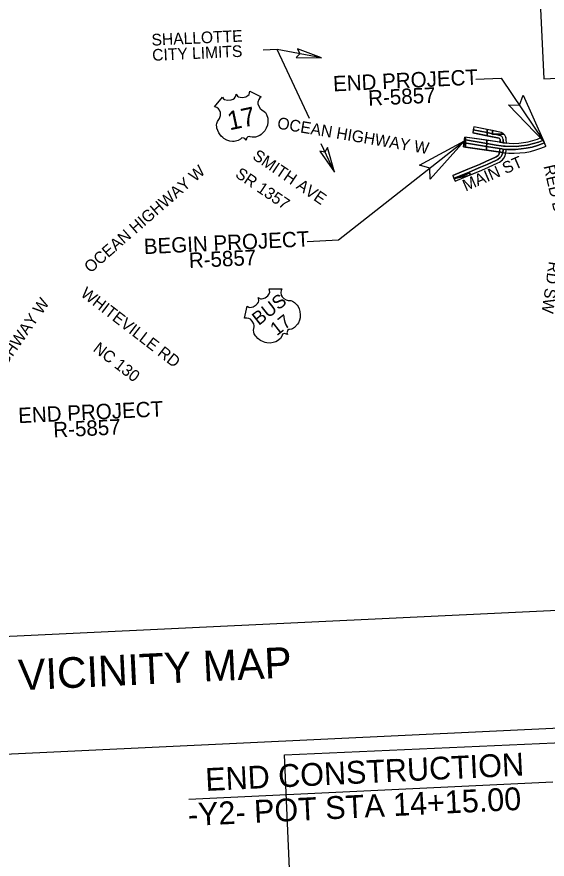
# Model space of a CAD drawing. Extents: x 2170913 to 2188101, y 74009 to 87693.
# Drawn here: x 2173761 to 2175486, y 78286 to 81028 of the extents above; entities that cross this region are included whole.
import ezdxf

# ---------------------------------------------------------------- set-up
doc = ezdxf.new("R2010")
doc.units = 0
for name, color, linetype in [('CTL Primary Horizontal and Vertical Cogo Elevation', 7, 'Continuous'), ('Exist Other Culture Fence Line', 7, 'Continuous'), ('Exist Property Iron Pin CELL', 7, 'Continuous'), ('Exist Right of Way Monument CELL', 7, 'Continuous'), ('Exist Structure Minor Pipes HDPE 30 Inch', 7, 'Continuous'), ('Exist Structure Minor Pipes RCP 15 Inch', 7, 'Continuous'), ('Exist Structure Minor Storm Sewer Manhole CELL', 7, 'Continuous'), ('Exist Utilities Water Fire Hydrant CELL', 7, 'Continuous')]:
    doc.layers.add(name, color=color, linetype=linetype)

msp = doc.modelspace()

# ---------------------------------------------------------------- linework, layer by layer
at = {"layer": 'CTL Primary Horizontal and Vertical Cogo Elevation'}
for p, q in [((2174607.1, 80921.5), (2174561.9, 80919.4)), ((2174752.1, 80894.4), (2174607.1, 80921.5)), ((2174712.2, 80696.8), (2174607.1, 80921.5)), ((2175253.5, 80824.7), (2175336.8, 80828.7)), ((2175336.8, 80828.7), (2175475.5, 80621.7)), ((2174807.2, 80302), (2175216.5, 80624.3)), ((2174793.6, 80522.8), (2174750.5, 80614.8)), ((2174705.2, 80297.1), (2174807.2, 80302)), ((2172841.7, 78585.3), (2175789.7, 78725.5))]:
    msp.add_line(p, q, dxfattribs=at)
for points in [[(2172704.4, 81472.7), (2175652.3, 81612.9), (2175771.5, 79107.1), (2172823.6, 78966.9)], [(2175652.3, 81612.9), (2175437.7, 81602.7), (2175474.6, 80826.6), (2175689.2, 80836.8)]]:
    msp.add_lwpolyline(points, close=True, dxfattribs=at)
at = {"layer": 'Exist Other Culture Fence Line'}
for points in [[(2174403.8, 80735.6), (2174429.7, 80767.1), (2174432.9, 80761.5), (2174435.7, 80759.3), (2174445.7, 80756.3), (2174457.6, 80757.6), (2174464.2, 80760.3), (2174468.2, 80763), (2174471.3, 80766.1), (2174474.5, 80774), (2174474.3, 80776.6), (2174478.8, 80769.8), (2174481.7, 80768.1), (2174486.8, 80766.3), (2174494.6, 80765.8), (2174505.1, 80768), (2174512, 80771.8), (2174516, 80775.7), (2174518.9, 80786.1), (2174555.4, 80767.9), (2174551.1, 80764.2), (2174547.5, 80759), (2174545.1, 80750.6), (2174545.1, 80744.6), (2174547.4, 80736.8), (2174552.1, 80729.8), (2174557.7, 80725.1), (2174565.1, 80720.4), (2174569.2, 80716.3), (2174573, 80710.3), (2174577.1, 80698.1), (2174577.6, 80692.6), (2174577.5, 80685), (2174575.8, 80675.7), (2174572, 80665.5), (2174567.4, 80657.4), (2174562.4, 80651.2), (2174555.3, 80644.6), (2174550.9, 80641.6), (2174537, 80636.4), (2174529.7, 80635.9), (2174525.8, 80636.3), (2174519.9, 80637.9), (2174517.7, 80638.7), (2174512.3, 80637.9), (2174508.7, 80634.3), (2174507.3, 80631.9), (2174506.2, 80626.3), (2174501.9, 80631.6), (2174498.7, 80633.5), (2174492.3, 80634.2), (2174487.7, 80630), (2174480.2, 80625.1), (2174467.8, 80621.9), (2174462.2, 80621.8), (2174453.3, 80623.1), (2174443.5, 80626.6), (2174434.2, 80632), (2174430.3, 80635.1), (2174425.5, 80639.6), (2174419.4, 80647.3), (2174417.3, 80650.7), (2174414, 80657.7), (2174411.7, 80665.4), (2174411.2, 80668.8), (2174410, 80676.4), (2174411.7, 80681.2), (2174413.8, 80687.5), (2174419.9, 80697), (2174421.4, 80700), (2174423.3, 80706.5), (2174423.1, 80716.4), (2174420.3, 80724), (2174416.4, 80729.1), (2174411.3, 80733), (2174404.3, 80735.5), (2174403.8, 80735.6), (2174429.7, 80767.1)], [(2174500.7, 80046.6), (2174510.1, 80086.2), (2174515.4, 80082.6), (2174518.9, 80081.9), (2174529.2, 80083.7), (2174539.4, 80090.1), (2174544, 80095.3), (2174546.4, 80099.6), (2174547.9, 80103.7), (2174547.3, 80112.2), (2174545.9, 80114.5), (2174553, 80110.4), (2174556.3, 80110), (2174561.7, 80110.8), (2174568.9, 80113.7), (2174577.3, 80120.3), (2174581.8, 80126.8), (2174583.7, 80132.1), (2174581.7, 80142.7), (2174622.5, 80142.5), (2174620.3, 80137.3), (2174619.3, 80131), (2174620.9, 80122.3), (2174623.6, 80117), (2174629.1, 80111), (2174636.3, 80106.8), (2174643.5, 80105.1), (2174652.2, 80104.1), (2174657.7, 80102.2), (2174663.7, 80098.6), (2174672.8, 80089.4), (2174675.8, 80084.7), (2174678.9, 80077.9), (2174681.5, 80068.8), (2174682.7, 80057.9), (2174682.1, 80048.6), (2174680.4, 80040.8), (2174676.9, 80031.8), (2174674.2, 80027.2), (2174664.1, 80016.3), (2174657.7, 80012.6), (2174654.1, 80011.3), (2174648, 80010.2), (2174645.7, 80009.9), (2174641.3, 80006.7), (2174639.6, 80001.9), (2174639.4, 79999.2), (2174640.9, 79993.6), (2174634.7, 79996.6), (2174631, 79996.9), (2174624.9, 79994.7), (2174622.7, 79988.9), (2174618.1, 79981.1), (2174608.4, 79972.8), (2174603.4, 79970.3), (2174594.9, 79967.5), (2174584.5, 79966.2), (2174573.8, 79967), (2174568.9, 79968.1), (2174562.6, 79970), (2174553.7, 79974.2), (2174550.3, 79976.4), (2174544.3, 79981.1), (2174538.9, 79987.1), (2174536.9, 79989.9), (2174532.5, 79996.2), (2174531.9, 80001.2), (2174531, 80007.8), (2174532.2, 80019.1), (2174532.3, 80022.4), (2174531.1, 80029.1), (2174526.6, 80037.8), (2174520.6, 80043.4), (2174514.9, 80046.2), (2174508.6, 80047.5), (2174501.2, 80046.7), (2174500.7, 80046.6), (2174510.1, 80086.2)]]:
    msp.add_lwpolyline(points, dxfattribs=at)
at = {"layer": 'Exist Property Iron Pin CELL'}
msp.add_line((2175504.9, 78536.7), (2174320.5, 78480.3), dxfattribs=at)
at = {"layer": 'Exist Right of Way Monument CELL'}
for p, q in [((2175247.7, 80670.2), (2175243.6, 80650.7)), ((2175245.7, 80660.4), (2175243.6, 80650.7)), ((2175247.7, 80670.2), (2175245.7, 80660.4)), ((2175333.1, 80642.3), (2175245.7, 80660.4)), ((2175245.7, 80660.4), (2175290.6, 80651.1)), ((2175290.6, 80651.1), (2175245.7, 80660.4)), ((2175337, 80651.5), (2175247.7, 80670.2)), ((2175291, 80661.1), (2175247.7, 80670.2)), ((2175290.2, 80641), (2175290.6, 80651.1)), ((2175290.6, 80651.1), (2175290.2, 80641)), ((2175290.6, 80651.1), (2175291, 80661.1)), ((2175291, 80661.1), (2175290.6, 80651.1)), ((2175290.6, 80651.1), (2175307.6, 80647.6)), ((2175307.6, 80647.6), (2175290.6, 80651.1)), ((2175307.9, 80657.6), (2175291, 80661.1)), ((2175307.6, 80647.6), (2175307.9, 80657.6)), ((2175307.9, 80657.6), (2175307.6, 80647.6)), ((2175217.2, 80627.9), (2175215.8, 80618.6)), ((2175218.2, 80635.1), (2175217.2, 80627.9)), ((2175217.2, 80627.9), (2175220.2, 80627.3)), ((2175220.2, 80627.3), (2175217.2, 80627.9)), ((2175218.4, 80636.6), (2175218.2, 80635.1)), ((2175220.3, 80634.8), (2175218.2, 80635.1)), ((2175289.6, 80626.2), (2175218.4, 80636.6)), ((2175220.1, 80617.8), (2175220.2, 80627.3)), ((2175220.2, 80627.3), (2175220.1, 80617.8)), ((2175220.2, 80627.3), (2175220.3, 80634.8)), ((2175220.2, 80627.3), (2175289.2, 80615.2)), ((2175289.2, 80615.2), (2175220.2, 80627.3)), ((2175330.1, 80632.7), (2175243.6, 80650.7)), ((2175243.6, 80650.7), (2175290.2, 80641)), ((2175289.6, 80626.2), (2175289.2, 80615.2)), ((2175289.2, 80615.2), (2175289.6, 80626.2)), ((2175346.3, 80617.9), (2175289.6, 80626.2)), ((2175290.2, 80641), (2175330.1, 80632.7)), ((2175307.6, 80647.6), (2175317.1, 80645.6)), ((2175317.1, 80645.6), (2175307.6, 80647.6)), ((2175307.6, 80647.6), (2175307.6, 80645.2)), ((2175307.6, 80645.2), (2175317.1, 80645.6)), ((2175317.1, 80645.6), (2175344.8, 80646.6)), ((2175344.8, 80646.6), (2175317.1, 80645.6)), ((2175333.1, 80642.3), (2175317.1, 80645.6)), ((2175317.1, 80645.6), (2175333.1, 80642.3)), ((2175333.3, 80617.9), (2175332.8, 80628.5)), ((2175332.8, 80628.5), (2175333.2, 80619.9)), ((2175343.3, 80618.4), (2175342.8, 80628.9)), ((2175343.3, 80618.4), (2175342.8, 80628.9)), ((2175342.8, 80628.9), (2175343.3, 80618.4)), ((2175353.3, 80617.1), (2175352.8, 80629.4)), ((2175353.3, 80617.1), (2175352.8, 80629.4)), ((2175457.8, 80620.6), (2175473.5, 80626.2)), ((2175473.5, 80626.2), (2175468.9, 80636.3)), ((2175477.5, 80617.4), (2175473.5, 80626.2)), ((2175215.8, 80618.6), (2175213.8, 80605)), ((2175213.8, 80605), (2175219.9, 80604.1)), ((2175215.8, 80618.6), (2175220.1, 80617.8)), ((2175220.1, 80617.8), (2175215.8, 80618.6)), ((2175219.9, 80604.1), (2175220.1, 80617.8)), ((2175220.1, 80617.8), (2175219.9, 80604.1)), ((2175219.9, 80604.1), (2175288.3, 80594.1)), ((2175288.3, 80594.1), (2175288.8, 80606.4)), ((2175288.8, 80606.4), (2175288.3, 80594.1)), ((2175288.8, 80606.4), (2175289.2, 80615.2)), ((2175289.2, 80615.2), (2175288.8, 80606.4)), ((2175288.8, 80606.4), (2175295.5, 80605.2)), ((2175295.5, 80605.2), (2175288.8, 80606.4)), ((2175295.5, 80605.2), (2175338.6, 80598.1)), ((2175333.2, 80619.9), (2175343.3, 80618.4)), ((2175338.6, 80598.1), (2175342.6, 80597.6)), ((2175356.7, 80596.4), (2175342.6, 80597.6)), ((2175343.3, 80618.4), (2175346.3, 80617.9)), ((2175343.4, 80607.3), (2175349.5, 80606.6)), ((2175349.5, 80606.6), (2175384.6, 80606)), ((2175482.1, 80607.1), (2175477.5, 80617.4)), ((2175288.3, 80594.1), (2175341.2, 80586.4)), ((2175341.2, 80586.4), (2175331.2, 80587.8)), ((2175341.2, 80586.4), (2175341.3, 80586.9)), ((2175341.3, 80586.9), (2175341.2, 80586.4)), ((2175341.2, 80586.4), (2175343.2, 80586.1)), ((2175343.2, 80586.1), (2175341.2, 80586.4)), ((2175325.6, 80563.5), (2175321.6, 80561.6)), ((2175232.8, 80518.7), (2175194.3, 80503.6)), ((2175235.9, 80513.4), (2175232.8, 80518.7)), ((2175178.7, 80511.2), (2175186.7, 80492.9)), ((2175178.7, 80511.2), (2175182.7, 80502)), ((2175182.7, 80502), (2175186.5, 80503.7)), ((2175186.5, 80503.7), (2175182.7, 80502)), ((2175182.7, 80502), (2175183, 80501.4)), ((2175183, 80501.4), (2175194.3, 80503.6)), ((2175194.3, 80503.6), (2175183.8, 80499.5)), ((2175183.8, 80499.5), (2175186.7, 80492.9)), ((2175186.7, 80492.9), (2175228, 80510.2)), ((2175228, 80510.2), (2175194.3, 80503.6)), ((2175194.3, 80503.6), (2175228, 80510.2)), ((2175228, 80510.2), (2175235.9, 80513.4))]:
    msp.add_line(p, q, dxfattribs=at)
for points in [[(2175337, 80651.5), (2175336.6, 80651.6), (2175307.9, 80657.6)], [(2175218.2, 80635.1), (2175220.3, 80634.8), (2175220.2, 80627.3)], [(2175317.1, 80645.6), (2175307.6, 80645.2), (2175307.6, 80647.6)], [(2175473.5, 80626.2), (2175457.8, 80620.6), (2175441.5, 80615.5), (2175420.9, 80610.7), (2175402, 80607.8), (2175384.6, 80606), (2175349.5, 80606.6), (2175343.4, 80607.3)], [(2175178.7, 80511.2), (2175228.1, 80531.9), (2175265.6, 80547.8), (2175286.7, 80556.6), (2175317.4, 80570.7), (2175320.2, 80572), (2175326.4, 80577), (2175328.3, 80579.2), (2175330.1, 80582.8), (2175331.5, 80588.8), (2175332.3, 80594.7), (2175332.7, 80598.4)], [(2175186.7, 80492.9), (2175235.9, 80513.4), (2175273.3, 80529.4), (2175294.7, 80538.3), (2175325.9, 80552.5), (2175330.9, 80554.9), (2175340.4, 80562.6), (2175345.2, 80568.2), (2175349, 80576), (2175351.1, 80585), (2175352.2, 80592.4), (2175352.6, 80596.7)], [(2175288.8, 80606.4), (2175223.9, 80617.2), (2175220.1, 80617.8)], [(2175220.1, 80617.8), (2175223.9, 80617.2), (2175288.8, 80606.4)], [(2175289.2, 80615.2), (2175319.7, 80609.9), (2175335.9, 80608.1), (2175343.4, 80607.3)], [(2175343.4, 80607.3), (2175335.9, 80608.1), (2175319.7, 80609.9), (2175289.2, 80615.2)], [(2175342.6, 80597.6), (2175338.6, 80598.1), (2175295.5, 80605.2)], [(2175341.3, 80586.9), (2175342.3, 80593.6), (2175342.6, 80597.6)], [(2175342.6, 80597.6), (2175342.3, 80593.6), (2175341.3, 80586.9)], [(2175342.6, 80597.6), (2175356.7, 80596.4), (2175382.8, 80596.5), (2175401.3, 80598), (2175417.3, 80600), (2175436.7, 80604.2), (2175455, 80609.5), (2175477.5, 80617.4)], [(2175401.3, 80598), (2175382.8, 80596.5), (2175356.7, 80596.4)], [(2175384.6, 80606), (2175402, 80607.8), (2175420.9, 80610.7), (2175441.5, 80615.5), (2175457.8, 80620.6)], [(2175477.5, 80617.4), (2175455, 80609.5), (2175436.7, 80604.2), (2175417.3, 80600), (2175401.3, 80598)], [(2175331.2, 80587.8), (2175330.1, 80582.8), (2175328.3, 80579.2), (2175326.4, 80577), (2175320.2, 80572), (2175317.4, 80570.7), (2175286.7, 80556.6), (2175265.6, 80547.8), (2175228.1, 80531.9), (2175178.7, 80511.2)], [(2175186.5, 80503.7), (2175232, 80522.7), (2175269.4, 80538.6), (2175290.7, 80547.4), (2175321.6, 80561.6), (2175325.6, 80563.5), (2175333.4, 80569.8), (2175336.8, 80573.7), (2175339.5, 80579.4), (2175341.2, 80586.4)], [(2175236, 80513.5), (2175273.3, 80529.4), (2175294.7, 80538.3), (2175325.9, 80552.5), (2175330.9, 80554.9), (2175340.4, 80562.6), (2175345.2, 80568.2), (2175349, 80576), (2175351.1, 80585)], [(2175341.2, 80586.4), (2175339.5, 80579.4), (2175336.8, 80573.7), (2175333.4, 80569.8), (2175325.6, 80563.5)], [(2175351.1, 80585), (2175351.1, 80585.2)], [(2175321.6, 80561.6), (2175290.7, 80547.4), (2175269.4, 80538.6)], [(2175269.4, 80538.6), (2175232, 80522.7), (2175186.5, 80503.7)], [(2175194.3, 80503.6), (2175232.8, 80518.7), (2175236, 80513.5), (2175236, 80513.5)]]:
    msp.add_lwpolyline(points, dxfattribs=at)
for centre, radius, start, end in [((2175327.8, 80628.2), 25, 2.7227, 69.2833), ((2175327.8, 80628.2), 25, 47.1323, 68.427), ((2175327.8, 80628.2), 5, 2.7227, 62.6876), ((2175327.8, 80628.2), 5, 2.7227, 62.6876), ((2175327.8, 80628.2), 15, 2.7227, 69.2833), ((2175327.8, 80628.2), 15, 2.7227, 69.2833), ((2175327.8, 80628.2), 15, 2.7227, 69.2833), ((2175327.8, 80628.2), 25, 2.7227, 47.1323), ((2175375.5, 80841.6), 225.5, 262.5611, 294.4661), ((2175375.8, 80839.6), 255.6, 262.6804, 294.5854), ((2175375.5, 80841.6), 225.5, 262.5611, 264.3613), ((2175375.8, 80839.6), 255.6, 262.6804, 264.4723)]:
    msp.add_arc(centre, radius, start, end, dxfattribs=at)
at = {"layer": 'Exist Structure Minor Pipes HDPE 30 Inch'}
msp.add_lwpolyline([(2174631.9, 78625), (2175899.9, 78682), (2175882.4, 79071.3), (2176656, 79297.5), (2177391.1, 79031.4), (2178152.3, 78655.2), (2178303.3, 76031.7), (2174802.3, 75830.2), (2174781.3, 76195.1), (2174799.2, 76231.4), (2174723.3, 76523.2)], close=True, dxfattribs=at)
at = {"layer": 'Exist Structure Minor Storm Sewer Manhole CELL'}
for points in [[(2174669.3, 80895.4), (2174752.1, 80894.4), (2174674.1, 80923.5), (2174681.7, 80907.4)], [(2175408, 80773), (2175475.5, 80621.7), (2175360, 80741.9), (2175395.7, 80740.8)], [(2175070.7, 80545.6), (2175216.5, 80624.3), (2175105.3, 80500.1), (2175103.8, 80535.8)], [(2174746.1, 80590.7), (2174793.6, 80522.8), (2174771.8, 80603.2), (2174763.1, 80587.6)]]:
    msp.add_lwpolyline(points, close=True, dxfattribs=at)
at = {"layer": 'Exist Utilities Water Fire Hydrant CELL'}
for p, q in [((2175213.8, 80605), (2175218.4, 80636.6)), ((2175346.3, 80617.9), (2175218.4, 80636.6)), ((2175482.1, 80607.1), (2175468.9, 80636.3)), ((2175343.2, 80586.1), (2175213.8, 80605))]:
    msp.add_line(p, q, dxfattribs=at)
for centre, radius, start, end in [((2175375.5, 80841.6), 225.5, 262.5611, 294.4661), ((2175375.8, 80839.6), 255.6, 262.6804, 294.5854)]:
    msp.add_arc(centre, radius, start, end, dxfattribs=at)

# ---------------------------------------------------------------- texts
at = {"layer": 'CTL Primary Horizontal and Vertical Cogo Elevation'}
for s, height, p in [('END PROJECT', 50, (2174790.5, 80785.3)), ('R-5857', 50, (2174904.6, 80738.6)), ('BEGIN PROJECT', 50, (2174174.9, 80255.3)), ('R-5857', 50, (2174321.3, 80210.1)), ('END PROJECT', 50, (2173766.1, 79705.1)), ('R-5857', 50, (2173880.2, 79658.4)), ('VICINITY MAP', 99.854, (2173767.7, 78835.2))]:
    msp.add_text(s, height=height, rotation=2.723, dxfattribs=at).set_placement(p)
at = {"layer": 'Exist Property Iron Pin CELL'}
for s, p in [('END CONSTRUCTION', (2174375.5, 78507.6)), ('-Y2- POT STA 14+15.00', (2174319, 78393.3))]:
    msp.add_text(s, height=74.313, rotation=2.8013, dxfattribs=at).set_placement(p)
at = {"layer": 'Exist Right of Way Monument CELL'}
for s, height, rotation, p in [('17', 60.75, 11.9787, (2174452.7, 80658.4)), ('BUS', 43.74, 38.1761, (2174547.5, 80021.5)), ('17', 43.74, 38.1761, (2174606.3, 79987.9))]:
    msp.add_text(s, height=height, rotation=rotation, dxfattribs=at).set_placement(p)
at = {"layer": 'Exist Structure Minor Pipes RCP 15 Inch'}
for s, rotation, p in [('SHALLOTTE', 2.5875, (2174199.6, 80934.2)), ('CITY LIMITS', 2.5875, (2174201.8, 80884.8)), ('OCEAN HIGHWAY W', 350.346, (2174605.9, 80664.7)), ('SMITH AVE', 325.9109, (2174524.4, 80567.6)), ('MAIN ST', 23.4807, (2175220.8, 80459.5)), ('OCEAN HIGHWAY W', 41.0946, (2174000.2, 80192.2)), ('RED BUG', 282.9278, (2175473.7, 80541.9)), ('SR 1357', 325.9109, (2174468.1, 80508.9)), ('RD SW', 261.9464, (2175491.5, 80233.3)), ('WHITEVILLE RD', 322.3551, (2173965.3, 80121.4)), ('OCEAN HIGHWAY W', 55.3425, (2173584.2, 79685.4)), ('NC 130', 322.3551, (2174005.7, 79941.9))]:
    msp.add_text(s, height=37.96, rotation=rotation, dxfattribs=at).set_placement(p)

doc.saveas('drawing.dxf')
